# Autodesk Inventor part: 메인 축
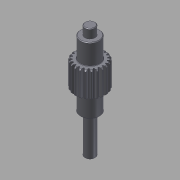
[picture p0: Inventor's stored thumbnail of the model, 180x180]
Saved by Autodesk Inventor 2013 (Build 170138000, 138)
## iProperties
Created: 2016-02
Part Number: 메인 축
Material: 강철, 연강
Document SubType Name: Modeling
Categories: <?xml version="1.0" encoding="UTF-16"?> <MemberInstance><Categories><FamilyTemplate><FamilyTemplateParameter ValueType="xs:double" Id="1" ObjectReferenceKey="da
Density: 7.86 g/cm^3
CustomPartVersion: 1
Author: mdu
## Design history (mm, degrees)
sketch "Sketch1"
  geometry: C1 r 12 at (0, 0)
  constraints: 1 centre point
  dimensions: "d0" = 24 diameter of C1 (= da_da)
extrude "Extrusion1" new body sketch "Sketch1" distance "d1" = 20 (= da_b); taper "d2" = 0 deg
workplane "Work Plane2"
feature "피치 지름" dims "d4" = 10, "d5" = 0
workplane "Work Plane8"
workplane "Work Plane9"
chamfer "모따기1" distance "d49" = 1; stored, may be unused: second distance "d50" = 2, angle "d51" = 45 deg
sketch "스케치3"
  geometry: C1 r 7.5 at (0, 0); 1 further point
  constraints: 1 centre point, 1 coincident
  dimensions: "d52" = 15 diameter of C1
extrude "돌출2" join sketch "스케치3" distance "d53" = 16; taper "d54" = 0 deg
sketch "스케치4"
  geometry: C1 r 4 at (0, 0); 1 further point
  constraints: 1 centre point, 1 coincident
  dimensions: "d55" = 8 diameter of C1
extrude "돌출3" join sketch "스케치4" distance "d56" = 7; taper "d57" = 0 deg
sketch "스케치5"
  geometry: C1 r 7.5 at (0, 0) reference; C2 r 7.5 at (0, 0) reference; 1 further point
extrude "돌출4" join sketch "스케치5" distance "d62" = 16; taper "d63" = 0 deg
sketch "스케치6"
  geometry: C1 r 4 at (0, 0); 1 further point
  constraints: 1 centre point, 1 coincident
  dimensions: "d64" = 8 diameter of C1
extrude "돌출5" join sketch "스케치6" distance "d65" = 30; taper "d66" = 0 deg
chamfer "모따기2" distance "d58" = 0.5; stored, may be unused: second distance "d59" = 2, angle "d60" = 45 deg
fillet "모깎기1" dims "d61" = 0.3
feature "스퍼 기어" dims "da_b" = 20, "da_d" = 22, "da_aw" = 31, "da_da" = 24, "da_df" = 19.5, "da_dw" = 22, angle "da_beta" = 0 deg, "da_lefttooth" = 0, "da_righttooth" = 0
body "Solid1"
sketch "Sketch2"
  geometry: C1 r 12 at (0, 0) reference; C2 r 11 at (0, 0)
  constraints: 1 centre point, 1 coincident
  dimensions: "d3" = 22 diameter of C2 (= da_dw)
body "Srf1"
node "투영된 루프1"
other parameters: "d16" = 31 (= da_aw), "d17" = 0, "d34" = 1.428 (computed from da_z), "d39" = 0, "d41" = 0, "d43" = 31 (= da_aw), "d46" = 31 (= da_aw), "d47" = 0, "d48" = 0
